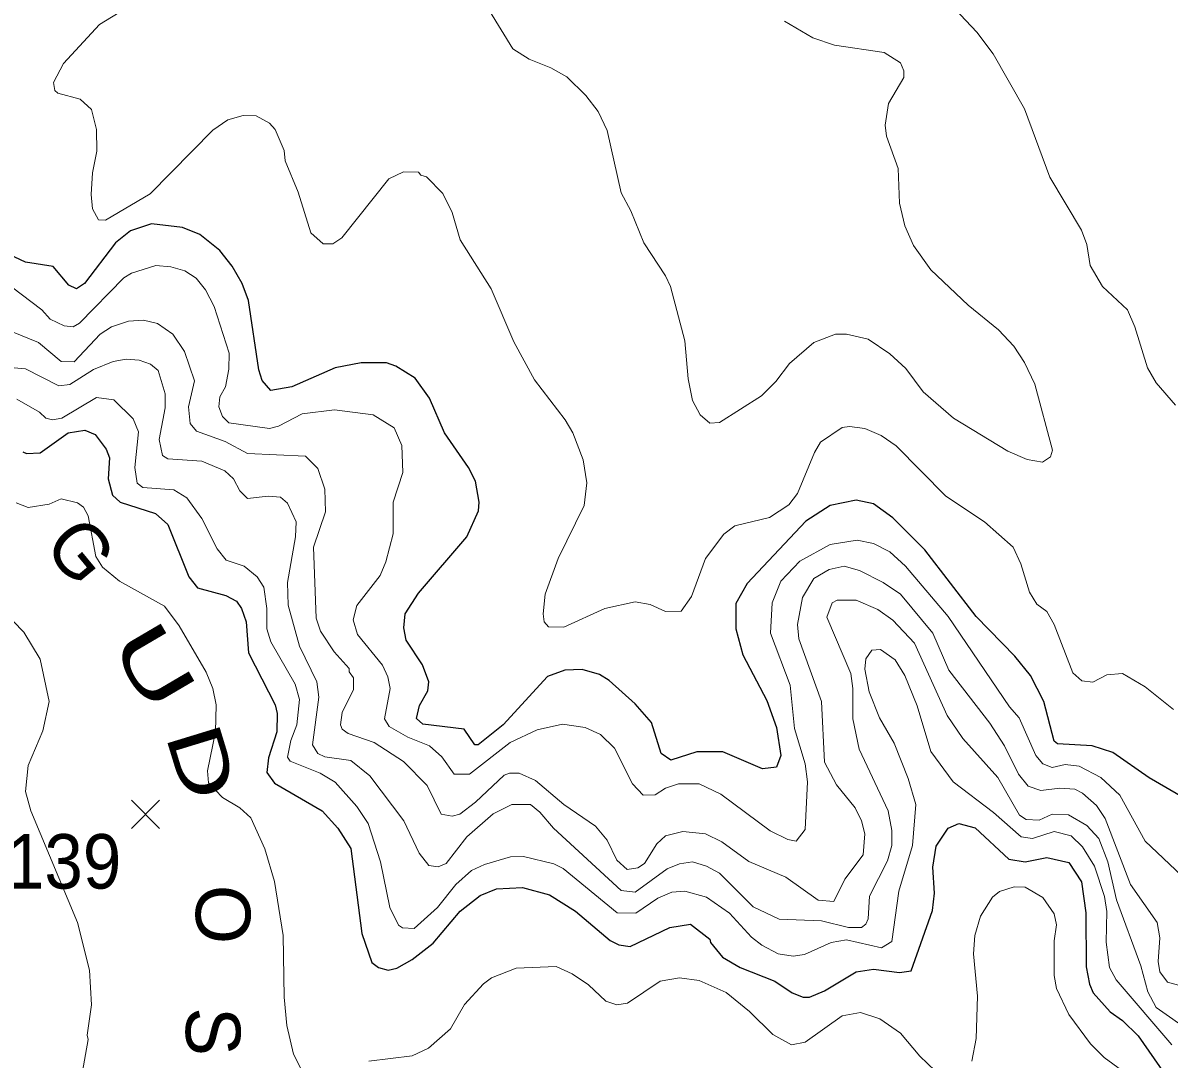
# Model space of a CAD drawing. Extents: x 265 to 291.4, y 7731.5 to 7759.6.
# Drawn here: x 268.324 to 270.007, y 7739.662 to 7741.184 of the extents above; entities that cross this region are included whole.
import ezdxf
from ezdxf.enums import TextEntityAlignment as Align

# ---------------------------------------------------------------- set-up
doc = ezdxf.new("R2010")
doc.units = 0
doc.header["$LTSCALE"] = 0.032
for name, color, linetype, lineweight in [('1', 7, 'Continuous', 25), ('2', 7, 'Continuous', 13), ('21', 7, 'Continuous', 25), ('61', 7, 'Continuous', 13)]:
    doc.layers.add(name, color=color, linetype=linetype, lineweight=lineweight)

msp = doc.modelspace()

# ---------------------------------------------------------------- linework, layer by layer
at = {"layer": '1'}
for points in [[(270.048, 7740.0343), (269.978, 7740.0748), (269.9247, 7740.1122), (269.8945, 7740.1218), (269.8436, 7740.1249), (269.8388, 7740.1289), (269.8237, 7740.187), (269.8038, 7740.2252), (269.7807, 7740.2538), (269.7243, 7740.3119), (269.6487, 7740.4098), (269.6018, 7740.4567), (269.5731, 7740.4773), (269.5477, 7740.4829), (269.5095, 7740.475), (269.4737, 7740.4519), (269.3878, 7740.3604), (269.3711, 7740.331), (269.3711, 7740.2936), (269.3814, 7740.2554), (269.4164, 7740.1886), (269.4307, 7740.1488), (269.4371, 7740.1075), (269.4307, 7740.0907), (269.4101, 7740.0883), (269.352, 7740.113), (269.3138, 7740.113), (269.2756, 7740.1011), (269.2613, 7740.1106), (269.247, 7740.156), (269.2231, 7740.1838), (269.1849, 7740.218), (269.1706, 7740.2268), (269.1452, 7740.2339), (269.1197, 7740.2331), (269.0943, 7740.2236), (269.029, 7740.1528), (268.9924, 7740.1234), (268.9877, 7740.1234), (268.9717, 7740.1464), (268.9113, 7740.1536), (268.9017, 7740.1623), (268.9065, 7740.1814), (268.9184, 7740.2029), (268.92, 7740.2157), (268.9105, 7740.2411), (268.8866, 7740.2769), (268.8834, 7740.2952), (268.885, 7740.3159), (268.9049, 7740.3461), (268.9757, 7740.4288), (268.9932, 7740.467), (268.994, 7740.4798), (268.9885, 7740.5107), (268.9781, 7740.5307), (268.9431, 7740.5816), (268.9208, 7740.6325), (268.9001, 7740.6619), (268.8715, 7740.6794), (268.858, 7740.6842), (268.8206, 7740.6842), (268.7824, 7740.677), (268.7188, 7740.6492), (268.6878, 7740.6436), (268.675, 7740.6587), (268.6702, 7740.6739), (268.6551, 7740.7757), (268.6456, 7740.8011), (268.6313, 7740.8266), (268.613, 7740.8496), (268.5836, 7740.8727), (268.5581, 7740.883), (268.5127, 7740.8886), (268.4817, 7740.8783), (268.4595, 7740.8608), (268.4141, 7740.8011), (268.4022, 7740.7931), (268.391, 7740.7987), (268.368, 7740.8258), (268.3274, 7740.8321), (268.3035, 7740.8433)], [(268.3234, 7740.5537), (268.329, 7740.5513), (268.3489, 7740.5521), (268.3902, 7740.5816), (268.4149, 7740.5855), (268.43, 7740.5792), (268.4459, 7740.5577), (268.4507, 7740.545), (268.4491, 7740.5139), (268.4555, 7740.4901), (268.4666, 7740.4797), (268.5183, 7740.463), (268.5366, 7740.4471), (268.5676, 7740.37), (268.5804, 7740.3541), (268.6217, 7740.3429), (268.6376, 7740.3342), (268.6448, 7740.3238), (268.6519, 7740.3039), (268.6551, 7740.2586), (268.6941, 7740.1822), (268.6973, 7740.1695), (268.6965, 7740.1425), (268.6846, 7740.1043), (268.6822, 7740.0828), (268.6933, 7740.0669), (268.7633, 7740.0263), (268.7864, 7740.0009), (268.8055, 7739.9714), (268.8214, 7739.8465), (268.8365, 7739.8036), (268.846, 7739.7964), (268.8604, 7739.7924), (268.8731, 7739.7956), (268.8954, 7739.8083), (268.9264, 7739.8322), (268.9662, 7739.8792), (268.9956, 7739.9022), (269.0195, 7739.9118), (269.0577, 7739.9141), (269.0974, 7739.903), (269.1356, 7739.8791), (269.1865, 7739.8362), (269.1993, 7739.8298), (269.216, 7739.8274), (269.274, 7739.8553), (269.3043, 7739.8601), (269.3329, 7739.8378), (269.3337, 7739.833), (269.3512, 7739.8115), (269.3774, 7739.7964), (269.4284, 7739.7765), (269.4538, 7739.759), (269.4697, 7739.7527), (269.4793, 7739.7527), (269.5015, 7739.7622), (269.5477, 7739.79), (269.5731, 7739.794), (269.6113, 7739.7892), (269.6288, 7739.7916), (269.6598, 7739.88), (269.663, 7739.9054), (269.6606, 7739.9436), (269.6654, 7739.9746), (269.6829, 7740.0009), (269.6988, 7740.008), (269.7227, 7740.0016), (269.772, 7739.9555), (269.7959, 7739.9515), (269.8277, 7739.9579)], [(269.8277, 7739.9579), (269.8603, 7739.9507), (269.8786, 7739.9221), (269.885, 7739.8768), (269.8857, 7739.7972), (269.8905, 7739.7718), (269.8961, 7739.759)], [(269.8961, 7739.759), (269.9207, 7739.7312), (269.9391, 7739.7185), (269.9621, 7739.6962), (270.009, 7739.6286)]]:
    msp.add_lwpolyline(points, dxfattribs=at)
at = {"layer": '2'}
for points in [[(268.7649, 7740.8592), (268.7466, 7740.8751), (268.7283, 7740.9348), (268.7092, 7740.9809), (268.7077, 7740.996), (268.6941, 7741.027), (268.6861, 7741.0366), (268.6663, 7741.0469), (268.6472, 7741.0477), (268.6249, 7741.0414), (268.6026, 7741.0262), (268.5104, 7740.9324), (268.4449, 7740.8939), (268.4346, 7740.8946), (268.426, 7740.9105), (268.424, 7740.9317), (268.426, 7740.9634), (268.4324, 7740.9952), (268.4316, 7741.027), (268.4245, 7741.0565), (268.4077, 7741.0716), (268.3751, 7741.0803), (268.3704, 7741.0843), (268.3688, 7741.0963), (268.3831, 7741.1241), (268.4364, 7741.1814), (268.4738, 7741.2044)], [(269.0091, 7741.2012), (269.0433, 7741.1456), (269.0672, 7741.1305), (269.099, 7741.1177), (269.1229, 7741.1042), (269.1507, 7741.0772), (269.169, 7741.0533), (269.1818, 7741.0255), (269.2024, 7740.934), (269.2168, 7740.9077), (269.2359, 7740.8608), (269.2677, 7740.8123), (269.2748, 7740.7964), (269.2963, 7740.7168), (269.3011, 7740.6611), (269.3074, 7740.6293), (269.3186, 7740.6078), (269.3329, 7740.5959), (269.3472, 7740.5967), (269.4085, 7740.6357), (269.4299, 7740.6571), (269.4498, 7740.6834), (269.4856, 7740.7144), (269.5175, 7740.7263), (269.5334, 7740.7263), (269.5652, 7740.7192), (269.597, 7740.6977), (269.6209, 7740.6762), (269.6463, 7740.642), (269.6909, 7740.603), (269.7704, 7740.5545), (269.7991, 7740.5426), (269.8213, 7740.5386), (269.8333, 7740.5466), (269.8364, 7740.5561), (269.8102, 7740.6532), (269.7951, 7740.685), (269.7792, 7740.7089), (269.7569, 7740.7327), (269.7123, 7740.7693), (269.6575, 7740.821), (269.632, 7740.8568), (269.6193, 7740.8855), (269.6113, 7740.9189), (269.6097, 7740.9698), (269.5922, 7741.0175), (269.5906, 7741.0334), (269.5954, 7741.0652), (269.6177, 7741.1034), (269.6177, 7741.113), (269.6129, 7741.1249), (269.589, 7741.14), (269.5159, 7741.1511), (269.484, 7741.1615), (269.4427, 7741.1861)], [(269.6925, 7741.2044), (269.7251, 7741.1702), (269.7489, 7741.1384), (269.7951, 7741.0573), (269.8325, 7740.957), (269.8786, 7740.8791), (269.8866, 7740.8584), (269.8913, 7740.8274), (269.9096, 7740.7964), (269.9462, 7740.7621), (269.9573, 7740.7375), (269.9756, 7740.677), (269.9884, 7740.6548), (270.017, 7740.6221)], [(268.9081, 7740.9602), (268.9049, 7740.9642), (268.8827, 7740.965), (268.8612, 7740.9547), (268.792, 7740.868), (268.7792, 7740.8592), (268.7649, 7740.8592)], [(270.0138, 7740.1751), (269.9725, 7740.2085), (269.9391, 7740.2284), (269.916, 7740.226), (269.8953, 7740.2156), (269.8794, 7740.2172), (269.8659, 7740.2292), (269.8388, 7740.3), (269.8277, 7740.3191), (269.8134, 7740.3302), (269.8022, 7740.3477), (269.7895, 7740.3891), (269.7784, 7740.4137), (269.7362, 7740.4511), (269.6797, 7740.4885), (269.6065, 7740.5625), (269.5843, 7740.5776), (269.5604, 7740.5879), (269.5381, 7740.5911), (269.527, 7740.5895), (269.4952, 7740.568), (269.4864, 7740.5529), (269.4618, 7740.4925), (269.449, 7740.4758), (269.4204, 7740.4575), (269.3695, 7740.4448), (269.3536, 7740.4328), (269.3265, 7740.397), (269.3058, 7740.3413), (269.2907, 7740.3199), (269.2677, 7740.3191), (269.2454, 7740.3294), (269.2231, 7740.3334), (269.1786, 7740.3238), (269.1181, 7740.296), (269.0958, 7740.2968), (269.0895, 7740.3039), (269.0879, 7740.3159), (269.0911, 7740.3445), (269.1102, 7740.397), (269.1483, 7740.475), (269.1523, 7740.5084), (269.1468, 7740.5418), (269.1316, 7740.5816), (269.1205, 7740.6007), (269.0752, 7740.6595), (269.0449, 7740.7152), (269.0115, 7740.7932), (268.9662, 7740.8648), (268.9542, 7740.9053), (268.9407, 7740.9332), (268.9168, 7740.9578), (268.9081, 7740.9602)], [(268.3069, 7740.7962), (268.3513, 7740.7624), (268.3639, 7740.7485), (268.3844, 7740.7385), (268.3973, 7740.7372), (268.4066, 7740.7425), (268.4722, 7740.8094), (268.4834, 7740.8161), (268.5192, 7740.8273), (268.541, 7740.8253), (268.5616, 7740.8194), (268.5781, 7740.8088), (268.5921, 7740.7916), (268.6046, 7740.767), (268.6265, 7740.6988), (268.6262, 7740.675), (268.6215, 7740.6492), (268.6129, 7740.6346), (268.6116, 7740.62), (268.6169, 7740.6054), (268.6262, 7740.5962), (268.6858, 7740.5882), (268.699, 7740.5915), (268.7341, 7740.6094), (268.7812, 7740.6154), (268.8381, 7740.6081), (268.8693, 7740.5889), (268.8802, 7740.5631), (268.8816, 7740.5234), (268.8676, 7740.4796), (268.8676, 7740.4333), (268.857, 7740.3922), (268.8484, 7740.3723), (268.8143, 7740.328), (268.809, 7740.3068), (268.815, 7740.2856), (268.852, 7740.2405), (268.86, 7740.2233), (268.8633, 7740.2061), (268.8547, 7740.1617), (268.8617, 7740.1505)], [(269.7863, 7740.0804), (269.7656, 7740.1218), (269.7442, 7740.1552), (269.6837, 7740.2332), (269.6606, 7740.2872), (269.6129, 7740.3445), (269.5875, 7740.362), (269.5525, 7740.3795), (269.5302, 7740.3859), (269.5079, 7740.3811), (269.4856, 7740.3676), (269.4689, 7740.3397), (269.4618, 7740.3), (269.4634, 7740.2793), (269.4968, 7740.187), (269.5015, 7740.0979), (269.519, 7740.0645), (269.5461, 7740.0311), (269.5556, 7740.012), (269.5604, 7739.9929), (269.558, 7739.9619), (269.531, 7739.9261), (269.5151, 7739.8935), (269.492, 7739.8951), (269.4443, 7739.9293), (269.3902, 7739.9523), (269.3504, 7739.981), (269.3265, 7739.9929), (269.2931, 7739.9961), (269.2677, 7739.9897), (269.2549, 7739.9778), (269.2366, 7739.9491), (269.2271, 7739.9428), (269.2112, 7739.9404), (269.1961, 7739.9539), (269.1818, 7739.9834), (269.165, 7740.0041), (269.1181, 7740.0359), (269.0767, 7740.0709), (269.0529, 7740.082), (269.0386, 7740.082), (269.0306, 7740.0788), (268.9885, 7740.039), (268.9654, 7740.0215), (268.9543, 7740.0184), (268.9383, 7740.0215), (268.9177, 7740.0637), (268.8826, 7740.0987), (268.8397, 7740.1266), (268.8015, 7740.1401), (268.7928, 7740.1464), (268.7904, 7740.1528), (268.7928, 7740.1711), (268.8095, 7740.2045), (268.8095, 7740.222), (268.8031, 7740.2307), (268.8031, 7740.2355), (268.7808, 7740.2602), (268.7609, 7740.2904), (268.7546, 7740.3095), (268.7506, 7740.4137), (268.7681, 7740.4654), (268.7673, 7740.4988), (268.757, 7740.5291), (268.7387, 7740.5474), (268.6536, 7740.5513), (268.6209, 7740.5688), (268.5788, 7740.584), (268.5692, 7740.5951), (268.5668, 7740.6198), (268.5756, 7740.6579), (268.5613, 7740.7009), (268.5438, 7740.7263), (268.5215, 7740.7423), (268.5008, 7740.747), (268.4786, 7740.7454), (268.4539, 7740.7375), (268.4372, 7740.7263), (268.399, 7740.6858), (268.3799, 7740.6866), (268.3465, 7740.7144), (268.3067, 7740.7303)], [(268.2486, 7740.6826), (268.3274, 7740.6754), (268.3767, 7740.6508), (268.3926, 7740.6524), (268.4276, 7740.6746), (268.4563, 7740.6866), (268.4754, 7740.6897), (268.4945, 7740.6882), (268.5112, 7740.6826), (268.5223, 7740.6731), (268.5326, 7740.6389), (268.5326, 7740.6182), (268.5239, 7740.572), (268.5286, 7740.5482), (268.5366, 7740.5434), (268.5867, 7740.5402), (268.6201, 7740.5259), (268.6329, 7740.5139), (268.6424, 7740.4965), (268.6536, 7740.4853), (268.6838, 7740.4885), (268.7021, 7740.4869), (268.7124, 7740.4781), (268.7251, 7740.4511), (268.7243, 7740.4288), (268.7124, 7740.362), (268.7132, 7740.3286), (268.7299, 7740.2682), (268.7554, 7740.2157), (268.7586, 7740.1934), (268.749, 7740.1234), (268.757, 7740.1106), (268.7673, 7740.1059), (268.8055, 7740.1003), (268.8333, 7740.078), (268.8834, 7740.012), (268.9057, 7739.9643), (268.92, 7739.946), (268.9336, 7739.9444), (268.9455, 7739.9492), (268.9757, 7739.9881), (269.0147, 7740.0223), (269.0418, 7740.0359), (269.0696, 7740.0359), (269.0831, 7740.0247), (269.103, 7740.0009), (269.2024, 7739.9094), (269.2231, 7739.907), (269.27, 7739.9412), (269.2884, 7739.9484), (269.3074, 7739.9515), (269.3281, 7739.9452), (269.3472, 7739.9348), (269.3965, 7739.8855), (269.4347, 7739.8672), (269.4968, 7739.8648), (269.5365, 7739.8553), (269.5556, 7739.8553), (269.562, 7739.8601), (269.5652, 7739.868), (269.5676, 7739.9014), (269.5938, 7739.9531), (269.6002, 7739.9754), (269.6002, 7739.9977), (269.5946, 7740.0263), (269.5524, 7740.117), (269.5429, 7740.1616), (269.5429, 7740.2061), (269.5397, 7740.2284), (269.5047, 7740.3111), (269.5127, 7740.3318), (269.5198, 7740.3358), (269.5477, 7740.3358), (269.5795, 7740.3222), (269.6018, 7740.3063), (269.6336, 7740.2729), (269.6813, 7740.1663), (269.7044, 7740.1329), (269.7561, 7740.0756), (269.7879, 7740.0199), (269.7975, 7740.0136), (269.8166, 7740.0128), (269.8356, 7740.0215), (269.8595, 7740.0208), (269.8866, 7740.0048), (269.9041, 7739.9858), (269.9176, 7739.9516), (269.9303, 7739.8959), (269.9661, 7739.7988), (269.9764, 7739.7606), (269.9884, 7739.7376), (270.0409, 7739.701)], [(268.3147, 7740.6309), (268.3481, 7740.6118), (268.3576, 7740.603), (268.3672, 7740.6007), (268.3807, 7740.6031), (268.4316, 7740.6333), (268.4571, 7740.6301), (268.4857, 7740.6023), (268.4937, 7740.5832), (268.4881, 7740.5307), (268.4913, 7740.5076), (268.5, 7740.5012), (268.5454, 7740.498), (268.5644, 7740.4861), (268.5867, 7740.4559), (268.609, 7740.4113), (268.6225, 7740.3946), (268.6488, 7740.3859), (268.6679, 7740.37), (268.6774, 7740.3548), (268.6822, 7740.3238), (268.6822, 7740.2936), (268.6878, 7740.2745), (268.7236, 7740.2125), (268.7299, 7740.1902), (268.7259, 7740.1528), (268.7172, 7740.1297), (268.7124, 7740.1051), (268.7164, 7740.0995), (268.7602, 7740.082), (268.7824, 7740.0685), (268.8142, 7740.0327), (268.8309, 7740.008), (268.8492, 7739.9516), (268.8628, 7739.8847), (268.8755, 7739.8585), (268.8811, 7739.8545), (268.8986, 7739.8537), (268.9328, 7739.8847), (268.9598, 7739.9181), (268.9829, 7739.9388), (269.002, 7739.9476), (269.0402, 7739.9587), (269.0593, 7739.9595), (269.1038, 7739.9484), (269.1173, 7739.942), (269.1969, 7739.8768), (269.2239, 7739.876), (269.2565, 7739.8982), (269.2772, 7739.907), (269.2963, 7739.9086), (269.3281, 7739.8998), (269.3615, 7739.876), (269.3941, 7739.841), (269.4093, 7739.829), (269.4331, 7739.8163), (269.4554, 7739.8131), (269.4721, 7739.8155), (269.5111, 7739.833), (269.5334, 7739.837), (269.5851, 7739.8251), (269.6002, 7739.8346), (269.6105, 7739.9086), (269.6304, 7739.9754), (269.6352, 7740.0359), (269.624, 7740.0741), (269.6034, 7740.1258), (269.5819, 7740.1632), (269.5668, 7740.2013), (269.5604, 7740.2347), (269.562, 7740.2499), (269.5707, 7740.2626), (269.5835, 7740.2634), (269.605, 7740.2483), (269.6193, 7740.2252), (269.6376, 7740.1807), (269.6575, 7740.1138)], [(268.4404, 7740.3843), (268.4308, 7740.4002), (268.4197, 7740.4598), (268.4125, 7740.4726), (268.4038, 7740.479), (268.3799, 7740.4845), (268.3624, 7740.4766), (268.3314, 7740.4718), (268.3139, 7740.4789)], [(268.8617, 7740.1505), (268.889, 7740.1345), (268.9208, 7740.1218), (268.9391, 7740.1059), (268.9574, 7740.0804), (268.9797, 7740.0804), (269.0394, 7740.1266), (269.0791, 7740.1456), (269.1165, 7740.1536), (269.1499, 7740.1488), (269.1722, 7740.1385), (269.1929, 7740.1186), (269.2191, 7740.0661), (269.2351, 7740.0494), (269.2526, 7740.0502), (269.2677, 7740.0597), (269.2868, 7740.0661), (269.317, 7740.0661), (269.3488, 7740.051), (269.4212, 7739.9969), (269.4475, 7739.9842), (269.4594, 7739.9818), (269.4729, 7739.9993), (269.4761, 7740.0693), (269.4729, 7740.0955), (269.457, 7740.1472), (269.4506, 7740.2109), (269.422, 7740.2872), (269.4244, 7740.3318), (269.4371, 7740.3636), (269.4649, 7740.393), (269.5095, 7740.4177), (269.5493, 7740.4241), (269.5731, 7740.4193), (269.597, 7740.4066), (269.6201, 7740.3859), (269.6829, 7740.3119), (269.7728, 7740.1791), (269.7871, 7740.1632), (269.8118, 7740.1075), (269.8221, 7740.0955), (269.8356, 7740.0899), (269.8547, 7740.0947), (269.8754, 7740.0923), (269.9072, 7740.0756), (269.9351, 7740.0494), (269.9725, 7739.9818), (270.0258, 7739.9317)], [(268.6074, 7740.1822), (268.6026, 7740.2061), (268.5931, 7740.23), (268.5533, 7740.2984), (268.5318, 7740.327), (268.4658, 7740.3636), (268.4404, 7740.3843)], [(268.2455, 7740.37), (268.325, 7740.2888), (268.3489, 7740.2491), (268.3624, 7740.187), (268.3529, 7740.1441), (268.3314, 7740.0931), (268.3274, 7740.055), (268.3354, 7740.0263), (268.4038, 7739.8625), (268.4213, 7739.7925), (268.4245, 7739.7415), (268.4181, 7739.697), (268.4197, 7739.6906), (268.4101, 7739.6381)], [(268.7347, 7739.6421), (268.7212, 7739.6692), (268.7116, 7739.7113), (268.7076, 7739.7527), (268.7061, 7739.8434), (268.6933, 7739.9229), (268.679, 7739.9706), (268.6583, 7740.016), (268.6424, 7740.0311), (268.617, 7740.0462), (268.5963, 7740.0677), (268.5947, 7740.0852), (268.6066, 7740.1425), (268.6074, 7740.1822)], [(269.6575, 7740.1138), (269.6901, 7740.0693), (269.7497, 7740.0239), (269.7903, 7739.9881), (269.807, 7739.9857), (269.8388, 7739.9961), (269.8635, 7739.9897)], [(269.9009, 7740.0343), (269.8802, 7740.0526), (269.8691, 7740.0581), (269.8468, 7740.0597), (269.8189, 7740.0565), (269.8006, 7740.0629), (269.7863, 7740.0804)], [(270.0536, 7739.7614), (270.0051, 7739.775), (269.9939, 7739.7901), (269.9916, 7739.8052), (269.9939, 7739.8402), (269.99, 7739.8625), (269.951, 7739.9181), (269.9136, 7740.0152), (269.9009, 7740.0343)], [(269.8635, 7739.9897), (269.8802, 7739.9738), (269.8977, 7739.9452), (269.9128, 7739.9006), (269.916, 7739.8784), (269.9152, 7739.8338), (269.92, 7739.7964), (269.9295, 7739.7781), (270.0114, 7739.6827)], [(269.9574, 7739.631), (269.912, 7739.6644), (269.8921, 7739.6843), (269.8603, 7739.7272), (269.842, 7739.7654), (269.8388, 7739.7845), (269.8388, 7739.8354), (269.842, 7739.8593), (269.8388, 7739.8752), (269.8221, 7739.8991), (269.7959, 7739.9142), (269.78, 7739.9149), (269.7585, 7739.9078), (269.7481, 7739.8998), (269.7306, 7739.872), (269.7219, 7739.8434), (269.7203, 7739.8163), (269.7259, 7739.7543), (269.7243, 7739.6922), (269.7179, 7739.6588)], [(269.675, 7739.6341), (269.6415, 7739.666), (269.6129, 7739.7002), (269.5827, 7739.7209), (269.554, 7739.7304), (269.527, 7739.7256), (269.4729, 7739.6866), (269.453, 7739.6827), (269.4252, 7739.6978), (269.391, 7739.732), (269.3568, 7739.7598), (269.317, 7739.7773), (269.2884, 7739.7813), (269.2597, 7739.7765), (269.212, 7739.7439), (269.1961, 7739.7415), (269.1802, 7739.7471), (269.1547, 7739.771), (269.1308, 7739.7869), (269.107, 7739.798), (269.0481, 7739.7956), (269.0123, 7739.7813), (269.0004, 7739.7726), (268.9725, 7739.7423), (268.9519, 7739.7065), (268.9193, 7739.6779), (268.8954, 7739.6668), (268.8317, 7739.6588)]]:
    msp.add_lwpolyline(points, dxfattribs=at)
at = {"layer": '21'}
for p, q in [((268.483, 7740.0419), (268.5242, 7740.0007)), ((268.5242, 7740.0419), (268.483, 7740.0007))]:
    msp.add_line(p, q, dxfattribs=at)

# ---------------------------------------------------------------- texts
at = {"layer": '61'}
for s, rotation, p in [('G', 309.697, (268.3783, 7740.383)), ('S', 270.451, (268.5631, 7739.7021))]:
    msp.add_text(s, height=0.08, rotation=rotation, dxfattribs=at).set_placement(p, align=Align.CENTER)
for s, rotation, width, p in [('U', 300.412, 1.6, (268.4818, 7740.2189)), ('D', 287.006, 1.4, (268.5484, 7740.0859)), ('O', 88.916, 1.05, (268.6578, 7739.8736))]:
    msp.add_text(s, height=0.08, rotation=rotation, dxfattribs=dict(at, width=width)).set_placement(p, align=Align.CENTER)
at = {"layer": '61', "width": 0.95}
msp.add_text('1139', height=0.08, dxfattribs=at).set_placement((268.3552, 7739.9123), align=Align.CENTER)

doc.saveas('drawing.dxf')
